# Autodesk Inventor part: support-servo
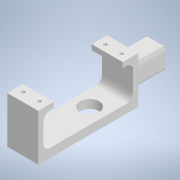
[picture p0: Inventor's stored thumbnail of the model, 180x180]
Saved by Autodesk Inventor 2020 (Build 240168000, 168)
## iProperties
Created: 2023-10
Part Number: support-servo
Material: Générique
Document SubType Name: Modeling
Designer: bruno
Density: 1 g/cm^3
Appearance: Par défaut
Author: bruno
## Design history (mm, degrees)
sketch "Esquisse1"
  geometry: L1 (0, 0)-(27, 0); L2 (27, -58)-(0, -58); L3 (0, -58)-(0, 0); L4 (20, -3)-(9, -3); L5 (5, -7)-(5, -51); L6 (9, -55)-(20, -55); L7 (24, -49)-(27, -49); L8 (24, -9)-(27, -9); L9 (24, -51)-(24, -49); L10 (24, -9)-(24, -7); L11 (27, 0)-(27, -9); L12 (27, -49)-(27, -58); A1 r 4 centre (20, -7) between (24, -7) and (20, -3); A2 r 4 centre (9, -7) between (9, -3) and (5, -7); A3 r 4 centre (9, -51) between (5, -51) and (9, -55); A4 r 4 centre (20, -51) between (20, -55) and (24, -51)
  constraints: 24 end point, 8 point on circle, 8 tangent, 7 perpendicular, 6 parallel, 4 centre point, 3 equal radius, 2 horizontal
  dimensions: "d0" = 27 distance of L2.start L2.end; "d1" = 58 distance of L1.end L2.start; "d2" = 5 distance between parallel lines of L3 L5; "d3" = 3 distance between parallel lines of L2 L6; "d4" = 3 distance between parallel lines of L1 L4; "d6" = 9 distance between parallel lines of L2 L7; "d7" = 9 distance between parallel lines of L1 L8; "d8" = 4 radius of A1
extrude "Extrusion1" new body sketch "Esquisse1" distance "d9" = 18; taper "d10" = 0 deg
sketch "Esquisse3"
  geometry: L1 (-15, 19)-(-3, 19); L2 (-3, 19)-(-3, 7); L3 (-3, 7)-(-15, 7); L4 (-15, 7)-(-15, 19); L5 (0, 0)-(-18, 0) reference; L6 (-18, 0)-(-18, 27) reference
  constraints: 8 end point, 2 parallel, 1 horizontal, 1 perpendicular
  dimensions: "d11" = 12 distance of L2.end L3.end; "d12" = 12 distance of L1.end L2.end; "d13" = 19 distance between parallel lines of L5 L1; "d14" = 3 distance between parallel lines of L6 L4
extrude "Extrusion2" join sketch "Esquisse3" distance "d15" = 20; taper "d16" = 0 deg
fillet "Congé1" dims "d17" = 2
chamfer "Chanfrein1" distance "d18" = 1; stored, may be unused: second distance "d19" = 2, angle "d20" = 45 deg
sketch "Esquisse4"
  geometry: C1 r 1 at (4.05, -43.823); C2 r 1 at (13.45, -43.823); C3 r 1 at (4.05, 3.823); C4 r 1 at (13.45, 3.823); A1 r 2.2 centre (4.05, -43.823) between (5.102, -45.755) and (2.998, -45.755) reference; A2 r 2.2 centre (13.45, -43.823) between (14.502, -45.755) and (12.398, -45.755) reference; A3 r 2.2 centre (13.45, 3.823) between (12.398, 5.755) and (14.502, 5.755) reference; A4 r 2.2 centre (4.05, 3.823) between (2.998, 5.755) and (5.102, 5.755) reference; 1 further point
  constraints: 4 centre point, 4 coincident
  dimensions: "d21" = 2 diameter of C1; "d22" = 2 diameter of C2; "d23" = 2 diameter of C3; "d24" = 2 diameter of C4
extrude "Extrusion3" cut sketch "Esquisse4" distance "d25" = 10; taper "d26" = 0 deg
sketch "Esquisse6"
  geometry: C1 r 5.5 at (8.782, 18.996); 1 further point
  constraints: 1 centre point
  dimensions: "d29" = 11 diameter of C1
extrude "Extrusion5" cut sketch "Esquisse6" distance "d30" = 10; taper "d31" = 0 deg
node "Solide1"
node "Référence1"
node "Référence2"
node "Référence3"
node "Référence4"
other parameters: "d5" = 3
